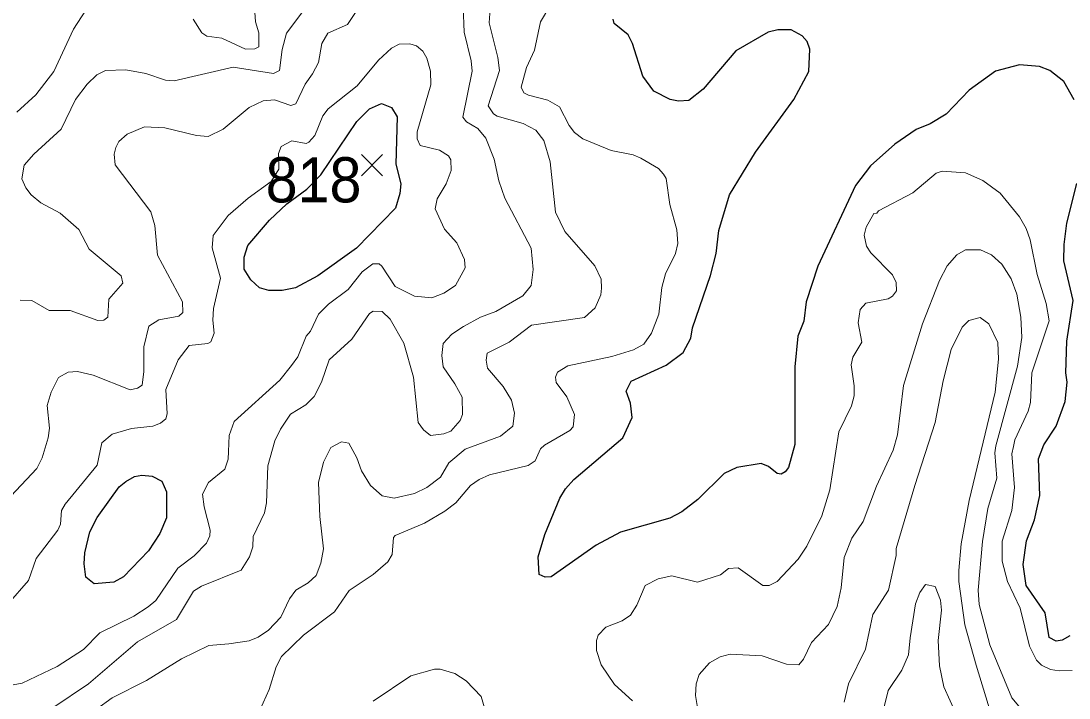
# Model space of a CAD drawing. Extents: x 294.2 to 320.3, y 7482.7 to 7510.7.
# Drawn here: x 315.127 to 316.982, y 7497.978 to 7499.176 of the extents above; entities that cross this region are included whole.
import ezdxf
from ezdxf.enums import TextEntityAlignment as Align

# ---------------------------------------------------------------- set-up
doc = ezdxf.new("R2010")
doc.units = 0
doc.header["$LTSCALE"] = 0.032
for name, color, linetype, lineweight in [('1', 7, 'Continuous', 25), ('2', 7, 'Continuous', 13), ('21', 7, 'Continuous', 25)]:
    doc.layers.add(name, color=color, linetype=linetype, lineweight=lineweight)
doc.layers.add('61', color=7, linetype='Continuous')

msp = doc.modelspace()

# ---------------------------------------------------------------- linework, layer by layer
at = {"layer": '1'}
for points in [[(316.7118, 7498.9835), (316.6741, 7498.9577), (316.6308, 7498.9195), (316.6042, 7498.8845), (316.5376, 7498.742), (316.5171, 7498.6791), (316.5126, 7498.6447), (316.5021, 7498.6184), (316.4969, 7498.5636), (316.4971, 7498.4266), (316.4855, 7498.3857), (316.4799, 7498.3781), (316.4727, 7498.3738), (316.4655, 7498.3749), (316.4505, 7498.3878), (316.4372, 7498.3927), (316.394, 7498.3857), (316.3718, 7498.375), (316.3252, 7498.3293), (316.2969, 7498.3072), (316.2758, 7498.2964), (316.1882, 7498.2712), (316.145, 7498.2486), (316.0657, 7498.1926), (316.0552, 7498.1916), (316.0446, 7498.1964), (316.0424, 7498.2276), (316.0541, 7498.2674), (316.0809, 7498.3315), (316.0909, 7498.3481), (316.1059, 7498.3643), (316.1923, 7498.4385), (316.209, 7498.474), (316.2062, 7498.4998), (316.1984, 7498.5208), (316.2073, 7498.5385), (316.2694, 7498.567), (316.2994, 7498.589), (316.3127, 7498.6148), (316.3155, 7498.6331), (316.3475, 7498.7257), (316.3577, 7498.7642), (316.3621, 7498.8051), (316.3815, 7498.868), (316.427, 7498.9438), (316.4952, 7499.0368), (316.5218, 7499.0863), (316.5234, 7499.1261), (316.5185, 7499.1395), (316.5101, 7499.1492), (316.4902, 7499.1599), (316.4669, 7499.1599), (316.4497, 7499.1562), (316.3926, 7499.1228), (316.3344, 7499.0551), (316.3094, 7499.0352), (316.2911, 7499.0336), (316.2762, 7499.0368), (316.2473, 7499.0513), (316.2279, 7499.0782), (316.2096, 7499.1357), (316.2018, 7499.1513), (316.1769, 7499.1712), (316.1752, 7499.1787)], [(316.9299, 7499.0953), (316.8944, 7499.098), (316.8523, 7499.0872), (316.8056, 7499.0534), (316.7645, 7499.0109), (316.7362, 7498.9937), (316.7118, 7498.9835)], [(316.9911, 7499.0361), (316.9731, 7499.0689), (316.9482, 7499.0883), (316.9299, 7499.0953)], [(316.9837, 7498.088), (316.9699, 7498.0804), (316.9593, 7498.0788), (316.9471, 7498.0853), (316.9399, 7498.1288), (316.9062, 7498.1773), (316.9011, 7498.2143), (316.9068, 7498.2559), (316.9209, 7498.2929), (316.9305, 7498.3363), (316.9285, 7498.4014), (316.9375, 7498.4257), (316.9592, 7498.4589), (316.9752, 7498.5023), (316.979, 7498.5368), (316.9764, 7498.5534), (316.9786, 7498.6092), (316.9897, 7498.6813), (316.973, 7498.7512), (316.9735, 7498.7802), (316.9785, 7498.8178), (316.9962, 7498.8883)]]:
    msp.add_lwpolyline(points, dxfattribs=at)
for points in [[(315.6528, 7498.7251), (315.6131, 7498.7037), (315.5895, 7498.699), (315.5659, 7498.699), (315.5494, 7498.7037), (315.5337, 7498.7179), (315.5219, 7498.7367), (315.5223, 7498.7579), (315.5286, 7498.7784), (315.5671, 7498.8232), (315.5978, 7498.8523), (315.6332, 7498.8782), (315.658, 7498.9034), (315.7215, 7498.9977), (315.7443, 7499.0205), (315.7655, 7499.03), (315.7828, 7499.0229), (315.793, 7499.0064), (315.7907, 7498.9222), (315.7993, 7498.8876), (315.7977, 7498.8703), (315.7899, 7498.8444), (315.7211, 7498.7739)], [(315.313, 7498.361), (315.3279, 7498.3697), (315.3413, 7498.372), (315.3594, 7498.3704), (315.3763, 7498.3618), (315.3849, 7498.3429), (315.3849, 7498.2966), (315.3731, 7498.269), (315.3527, 7498.2384), (315.3088, 7498.1924), (315.2915, 7498.1829), (315.2569, 7498.1798), (315.242, 7498.1916), (315.2388, 7498.2152), (315.2404, 7498.2348), (315.2493, 7498.2718), (315.2621, 7498.2973), (315.2843, 7498.3287), (315.3011, 7498.3515)]]:
    msp.add_lwpolyline(points, close=True, dxfattribs=at)
at = {"layer": '2'}
for points in [[(315.1197, 7499.0143), (315.1536, 7499.045), (315.1855, 7499.0865), (315.22, 7499.1612), (315.2729, 7499.2429)], [(315.432, 7499.179), (315.4473, 7499.1548), (315.4562, 7499.1491), (315.4824, 7499.1452), (315.5246, 7499.1261), (315.5412, 7499.1267), (315.5482, 7499.1299), (315.5482, 7499.1548), (315.5424, 7499.174), (315.5386, 7499.2263)], [(315.3202, 7498.5234), (315.3336, 7498.5259), (315.3419, 7498.5317), (315.3445, 7498.5559), (315.3445, 7498.5994), (315.3534, 7498.6357), (315.3713, 7498.6472), (315.4064, 7498.6536), (315.4134, 7498.66), (315.4128, 7498.6791), (315.3687, 7498.7615), (315.3643, 7498.8139), (315.3572, 7498.8381), (315.2941, 7498.9211), (315.2921, 7498.9403), (315.2953, 7498.9518), (315.3004, 7498.9626), (315.3151, 7498.9754), (315.3458, 7498.9882), (315.3815, 7498.9869), (315.4377, 7498.9729), (315.4582, 7498.9716), (315.4849, 7498.9843), (315.5309, 7499.0227), (315.5558, 7499.0347), (315.5756, 7499.036), (315.605, 7499.0265), (315.6139, 7499.029), (315.6299, 7499.0642), (315.6433, 7499.082), (315.6535, 7499.1025), (315.6599, 7499.1357), (315.6701, 7499.1542), (315.7052, 7499.1695), (315.7359, 7499.2161)], [(315.1255, 7498.6817), (315.1466, 7498.681), (315.1772, 7498.6638), (315.2143, 7498.6638), (315.2634, 7498.646), (315.2736, 7498.6466), (315.2806, 7498.6517), (315.2825, 7498.6836), (315.3074, 7498.7117), (315.3043, 7498.7251), (315.2481, 7498.7723), (315.2295, 7498.8068), (315.1964, 7498.8356), (315.1625, 7498.8541), (315.1453, 7498.8681), (315.1357, 7498.8803), (315.1287, 7498.8962), (315.1325, 7498.9205), (315.1497, 7498.9403), (315.1983, 7498.9843), (315.2238, 7499.0367), (315.2442, 7499.0641), (315.2615, 7499.0807), (315.2768, 7499.0884), (315.3126, 7499.0891), (315.3483, 7499.0826), (315.3828, 7499.0712), (315.3981, 7499.0699), (315.5028, 7499.0942), (315.5744, 7499.0827), (315.5845, 7499.0884), (315.5896, 7499.1255), (315.5973, 7499.1542), (315.6312, 7499.1995)], [(315.9574, 7499.197), (315.9561, 7499.1727), (315.9714, 7499.1114), (315.974, 7499.0884), (315.9542, 7499.0259), (315.9638, 7499.0112), (315.9702, 7499.0073), (316.0162, 7498.9946), (316.0385, 7498.9824), (316.0526, 7498.9646), (316.0641, 7498.9263), (316.073, 7498.8375), (316.0896, 7498.8036), (316.1426, 7498.7424), (316.1541, 7498.7187), (316.1547, 7498.7028), (316.1534, 7498.6913), (316.1432, 7498.6683), (316.1247, 7498.6511), (316.0308, 7498.6376), (315.9912, 7498.6076), (315.9523, 7498.5878), (315.9504, 7498.5757), (315.953, 7498.5617), (315.9804, 7498.5291), (315.9951, 7498.5049), (316.0008, 7498.4819), (315.9977, 7498.4589), (315.9759, 7498.441), (315.9133, 7498.418), (315.8846, 7498.3938), (315.87, 7498.3688), (315.8457, 7498.3503), (315.8234, 7498.3395), (315.7876, 7498.3318), (315.7665, 7498.3356), (315.7461, 7498.3542), (315.7301, 7498.3797), (315.7218, 7498.4027), (315.7072, 7498.4289), (315.6944, 7498.4314), (315.6758, 7498.4212), (315.6624, 7498.395), (315.6535, 7498.3593), (315.656, 7498.2993), (315.6624, 7498.2418), (315.658, 7498.2163), (315.6496, 7498.1945), (315.6356, 7498.1818), (315.6139, 7498.169), (315.6024, 7498.1537), (315.5871, 7498.1211), (315.5654, 7498.0981), (315.5469, 7498.0854), (315.5309, 7498.079), (315.4952, 7498.0739), (315.4594, 7498.0707), (315.4115, 7498.0471), (315.3496, 7498.0088), (315.2883, 7497.9781), (315.2609, 7497.9583)], [(315.9101, 7499.2008), (315.9114, 7499.1561), (315.9242, 7499.105), (315.9255, 7499.0872), (315.9095, 7499.0054), (315.9159, 7498.9971), (315.9357, 7498.9856), (315.9498, 7498.9683), (315.9645, 7498.9314), (315.9727, 7498.8931), (315.9836, 7498.8624), (316.0302, 7498.7736), (316.034, 7498.736), (316.0302, 7498.7079), (316.0155, 7498.6894), (315.9677, 7498.6619), (315.9408, 7498.6517), (315.9102, 7498.6351), (315.8898, 7498.6217), (315.8744, 7498.6051), (315.8718, 7498.584), (315.8744, 7498.5636), (315.8948, 7498.5336), (315.9083, 7498.51), (315.9089, 7498.4793), (315.9044, 7498.4691), (315.8878, 7498.4499), (315.8757, 7498.4455), (315.8521, 7498.4422), (315.8399, 7498.4525), (315.8304, 7498.4653), (315.822, 7498.5457), (315.8048, 7498.6057), (315.7806, 7498.6485), (315.7665, 7498.6619), (315.7506, 7498.6626), (315.7442, 7498.658), (315.7129, 7498.6127), (315.6727, 7498.5763), (315.6593, 7498.5368), (315.6458, 7498.5112), (315.6311, 7498.4966), (315.6043, 7498.48), (315.5867, 7498.4538), (315.5762, 7498.4329), (315.5641, 7498.3887), (315.5615, 7498.3235)], [(316.0634, 7499.2021), (316.0468, 7499.174), (316.036, 7499.1242), (316.0219, 7499.0935), (316.0123, 7499.0584), (316.0174, 7499.0488), (316.0257, 7499.0444), (316.0596, 7499.0354), (316.0806, 7499.0239), (316.0973, 7498.9907), (316.1068, 7498.9786), (316.1215, 7498.9671), (316.172, 7498.9466), (316.2109, 7498.939), (316.2243, 7498.9333), (316.2556, 7498.9147), (316.2645, 7498.9045), (316.269, 7498.8969), (316.2754, 7498.8509), (316.2881, 7498.8062)], [(315.1044, 7498.1448), (315.1402, 7498.1856), (315.1542, 7498.2246), (315.1925, 7498.275), (315.197, 7498.2858), (315.1989, 7498.3095), (315.2053, 7498.321), (315.2621, 7498.3899), (315.2704, 7498.4295), (315.2883, 7498.4448), (315.3228, 7498.455), (315.3604, 7498.4588), (315.3739, 7498.464), (315.3834, 7498.4717), (315.386, 7498.4806), (315.3834, 7498.524), (315.4051, 7498.5764), (315.4249, 7498.6019), (315.4581, 7498.6051), (315.4633, 7498.6083), (315.469, 7498.6236), (315.467, 7498.6466), (315.4677, 7498.667), (315.4805, 7498.7207), (315.4658, 7498.7743), (315.4671, 7498.796), (315.4939, 7498.8317), (315.529, 7498.8624), (315.5697, 7498.8915), (315.5836, 7498.9136), (315.583, 7498.9415), (315.5877, 7498.9537), (315.6063, 7498.9639), (315.6318, 7498.9588), (315.6369, 7498.9613), (315.6471, 7498.9729), (315.6612, 7499.008), (315.6707, 7499.0201), (315.7224, 7499.0609), (315.7601, 7499.1063), (315.7831, 7499.1274), (315.7965, 7499.135), (315.8157, 7499.1356), (315.8272, 7499.1318), (315.8387, 7499.1222), (315.8457, 7499.1101), (315.8521, 7499.0872), (315.8527, 7499.0629), (315.8284, 7498.9799), (315.8284, 7498.9671), (315.8335, 7498.9556), (315.8681, 7498.9473), (315.884, 7498.9371), (315.8878, 7498.9301), (315.8884, 7498.9115), (315.8795, 7498.8879), (315.8636, 7498.8611), (315.8603, 7498.8433), (315.877, 7498.8075), (315.8987, 7498.7832), (315.9121, 7498.7539), (315.9134, 7498.7392), (315.8961, 7498.7079), (315.8757, 7498.6945), (315.8546, 7498.6861), (315.8234, 7498.6887), (315.7895, 7498.706), (315.7659, 7498.7417), (315.7614, 7498.7462), (315.7499, 7498.7462), (315.7308, 7498.7322)], [(316.5972, 7498.4946), (316.6017, 7498.5125), (316.6017, 7498.5304), (316.5965, 7498.5674), (316.5997, 7498.5808), (316.6157, 7498.6076), (316.6093, 7498.6415), (316.6125, 7498.6651), (316.6227, 7498.6766), (316.6623, 7498.6843), (316.67, 7498.6887), (316.677, 7498.6983), (316.6763, 7498.713), (316.6697, 7498.7269), (316.6312, 7498.7653), (316.6237, 7498.7776), (316.6197, 7498.7971), (316.6232, 7498.811), (316.637, 7498.8352), (316.6419, 7498.8355), (316.645, 7498.8401), (316.7057, 7498.872), (316.7472, 7498.9064), (316.7574, 7498.9103), (316.799, 7498.9071), (316.8296, 7498.8937), (316.8602, 7498.8713), (316.8947, 7498.8292), (316.9062, 7498.8088), (316.9132, 7498.7883), (316.926, 7498.727), (316.9419, 7498.676), (316.947, 7498.6453), (316.9164, 7498.5534), (316.9138, 7498.501), (316.91, 7498.4857), (316.8864, 7498.4346), (316.8839, 7498.4231), (316.8813, 7498.4097), (316.886, 7498.3502), (316.8813, 7498.3095), (316.864, 7498.2552), (316.864, 7498.2201), (316.8736, 7498.1843), (316.896, 7498.1371), (316.912, 7498.0694), (316.9247, 7498.0451), (316.9337, 7498.0362), (316.9496, 7498.0285), (316.965, 7498.026), (316.9879, 7498.0266)], [(316.2881, 7498.8062), (316.2901, 7498.782), (316.2856, 7498.7641), (316.2677, 7498.7283), (316.2613, 7498.7041), (316.2562, 7498.6568), (316.2434, 7498.6236)], [(316.3379, 7497.8799), (316.3213, 7497.9826), (316.322, 7498.003), (316.3277, 7498.0196), (316.3456, 7498.04), (316.3648, 7498.0509), (316.3827, 7498.0553), (316.4388, 7498.0528), (316.4822, 7498.0381), (316.504, 7498.0368), (316.5123, 7498.0464), (316.5263, 7498.0764), (316.5563, 7498.1083), (316.5716, 7498.1397), (316.5787, 7498.1729), (316.5844, 7498.2265), (316.5978, 7498.261), (316.6176, 7498.2903), (316.6412, 7498.3529), (316.6712, 7498.4167), (316.6789, 7498.4436), (316.6891, 7498.531), (316.723, 7498.6402), (316.7529, 7498.7168), (316.7664, 7498.7424), (316.7836, 7498.7622), (316.799, 7498.7711), (316.8258, 7498.7711), (316.8449, 7498.7622), (316.8634, 7498.7455), (316.88, 7498.7194), (316.8896, 7498.6926), (316.8972, 7498.6517), (316.8985, 7498.616), (316.8908, 7498.5649), (316.8525, 7498.4244), (316.8507, 7498.4116), (316.8545, 7498.3669), (316.8385, 7498.3133), (316.8289, 7498.2546), (316.8213, 7498.169), (316.8232, 7498.1435), (316.8423, 7498.072), (316.8812, 7497.9782), (316.9173, 7497.9348)], [(315.7308, 7498.7322), (315.7065, 7498.7009), (315.6714, 7498.6746), (315.6535, 7498.6568), (315.6395, 7498.6268), (315.6318, 7498.6179), (315.6171, 7498.5815)], [(316.8628, 7497.8894), (316.8181, 7498.0362), (316.7976, 7498.1077), (316.7874, 7498.1843), (316.7874, 7498.2035), (316.7912, 7498.2507), (316.8053, 7498.3274), (316.8513, 7498.5189), (316.8576, 7498.5776), (316.8564, 7498.607), (316.8404, 7498.6402), (316.8251, 7498.6511), (316.8047, 7498.646), (316.7932, 7498.6338), (316.7739, 7498.5945), (316.7596, 7498.5394), (316.7453, 7498.4653), (316.7095, 7498.3542), (316.6763, 7498.2424), (316.6763, 7498.2303), (316.6629, 7498.169), (316.6349, 7498.1256), (316.6221, 7498.0643), (316.592, 7498.003), (316.5844, 7497.9704)], [(316.2434, 7498.6236), (316.2294, 7498.6038), (316.2116, 7498.5942), (316.1732, 7498.5821), (316.0953, 7498.5655), (316.0768, 7498.5546), (316.073, 7498.5457), (316.0743, 7498.5361), (316.0934, 7498.5106), (316.1068, 7498.4793), (316.1043, 7498.4576), (316.0985, 7498.4512), (316.0538, 7498.425), (316.0468, 7498.4186), (316.0372, 7498.3975), (316.0251, 7498.3893), (315.9562, 7498.3727), (315.9383, 7498.3644), (315.9229, 7498.3542), (315.8968, 7498.3235), (315.8776, 7498.3088), (315.8412, 7498.2871), (315.7895, 7498.2654), (315.7863, 7498.2622), (315.7844, 7498.2316), (315.7767, 7498.2188), (315.7506, 7498.1965), (315.7082, 7498.1683), (315.6818, 7498.1304), (315.6273, 7498.0892), (315.5884, 7498.0515), (315.5788, 7498.033), (315.5667, 7497.9928), (315.5401, 7497.9342)], [(315.6171, 7498.5815), (315.6062, 7498.5662), (315.5852, 7498.54), (315.5047, 7498.4672), (315.4958, 7498.4423), (315.4945, 7498.4142)], [(315.1733, 7498.4952), (315.1804, 7498.5189), (315.1938, 7498.5451), (315.2104, 7498.5546), (315.227, 7498.5559), (315.2551, 7498.5489), (315.3202, 7498.5234)], [(315.1089, 7498.335), (315.1549, 7498.3842), (315.1644, 7498.4027), (315.1753, 7498.4385), (315.1779, 7498.4551), (315.1733, 7498.4952)], [(316.4657, 7498.1843), (316.5027, 7498.2239), (316.518, 7498.2469), (316.5448, 7498.3005), (316.5589, 7498.3465), (316.5748, 7498.4487), (316.5972, 7498.4946)], [(315.4945, 7498.4142), (315.4939, 7498.4008), (315.4881, 7498.3829), (315.4588, 7498.3592), (315.4486, 7498.3388), (315.4511, 7498.3159), (315.4619, 7498.275), (315.4613, 7498.2648), (315.4556, 7498.252), (315.4338, 7498.2297), (315.4045, 7498.2079), (315.3656, 7498.1505), (315.3521, 7498.139), (315.3266, 7498.123), (315.2666, 7498.093), (315.2379, 7498.0637), (315.1913, 7498.0336), (315.1293, 7498.0043), (315.1006, 7497.9991)], [(315.5615, 7498.3235), (315.5584, 7498.3057), (315.538, 7498.2635), (315.5373, 7498.2456), (315.5316, 7498.2278), (315.5168, 7498.2041), (315.4467, 7498.176)], [(316.2096, 7497.973), (316.1777, 7498.0017), (316.154, 7498.0368), (316.1458, 7498.0618), (316.1458, 7498.0796), (316.149, 7498.0892), (316.1624, 7498.1032), (316.1911, 7498.1147), (316.2058, 7498.1243), (316.2173, 7498.1422), (316.232, 7498.1773), (316.255, 7498.1888), (316.2792, 7498.1939), (316.3245, 7498.1831), (316.3653, 7498.1959), (316.3796, 7498.207), (316.3967, 7498.208), (316.4401, 7498.1773), (316.4516, 7498.1773), (316.4657, 7498.1843)], [(315.4467, 7498.176), (315.4326, 7498.1671), (315.4026, 7498.1167), (315.3336, 7498.0771), (315.2468, 7498.003), (315.1836, 7497.9608)], [(316.6406, 7497.9053), (316.6623, 7497.9915), (316.6865, 7498.0273), (316.698, 7498.0541), (316.7013, 7498.0847), (316.7102, 7498.1448), (316.7179, 7498.1645), (316.728, 7498.1786), (316.7453, 7498.1754), (316.7549, 7498.1511), (316.7568, 7498.1333), (316.7504, 7498.0796), (316.7529, 7498.0349), (316.7606, 7497.9979), (316.783, 7497.9481)], [(315.7507, 7497.9726), (315.8173, 7498.0172), (315.8591, 7498.0292), (315.8693, 7498.0292), (315.8949, 7498.0215), (315.9153, 7498.0081), (315.9415, 7497.9806), (315.9548, 7497.9366)]]:
    msp.add_lwpolyline(points, dxfattribs=at)
at = {"layer": '21'}
for p, q in [((315.7297, 7498.9394), (315.7672, 7498.9019)), ((315.7672, 7498.9394), (315.7297, 7498.9019))]:
    msp.add_line(p, q, dxfattribs=at)

# ---------------------------------------------------------------- texts
at = {"layer": '61', "width": 0.95}
msp.add_text('818', height=0.08, dxfattribs=at).set_placement((315.645, 7498.8548), align=Align.CENTER)

doc.saveas('drawing.dxf')
